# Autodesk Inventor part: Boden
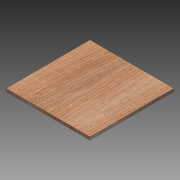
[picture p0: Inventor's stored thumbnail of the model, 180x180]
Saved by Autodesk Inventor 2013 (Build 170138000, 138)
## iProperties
Created: 2012-07
Part Number: Boden
Material: Holz (Birke)
Document SubType Name: Modeling
Designer: rYan
Mass: 495 g
Surface Area: 1920 cm^2
Volume: 900 cm^3
Density: 0.55 g/cm^3
Author: rYan
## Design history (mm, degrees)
sketch "Skizze1"
  geometry: L1 (-150, -150)-(150, -150); L2 (150, -150)-(150, 150); L3 (150, 150)-(-150, 150); L4 (-150, 150)-(-150, -150); L5 (-150, -150)-(150, 150); L6 (150, -150)-(-150, 150); 1 further point
  constraints: 12 end point, 2 midpoint, 2 parallel, 1 horizontal, 1 perpendicular
  dimensions: "d0" = 300 distance of L2.end L3.end; "d1" = 300 distance of L3.end L1.start
extrude "Extrusion1" new body sketch "Skizze1" distance "d2" = 10; taper "d3" = 0 deg
node "Volumenkörper1"
